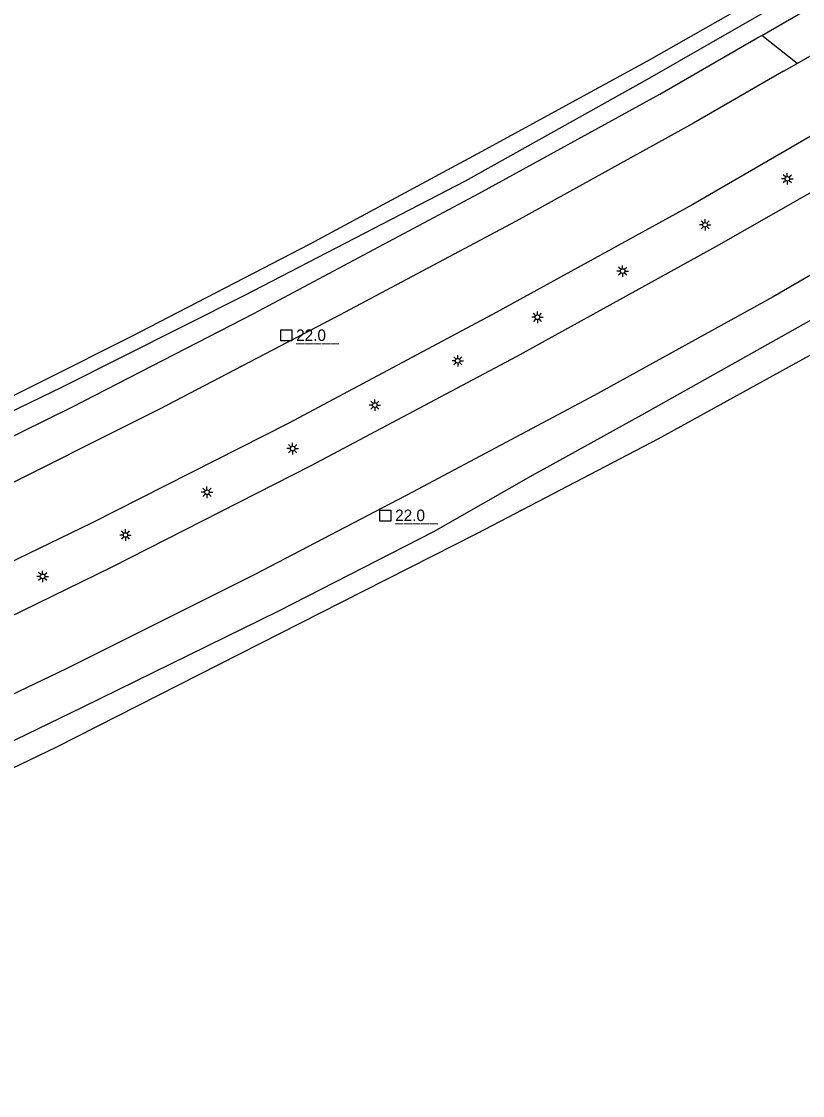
# Model space of a CAD drawing. Extents: x 124000 to 129000, y 395500 to 397503.
# Drawn here: x 125483 to 125568.1, y 397250 to 397367.1 of the extents above; entities that cross this region are included whole.
import ezdxf

# ---------------------------------------------------------------- set-up
doc = ezdxf.new("R2010")
doc.units = 0
for name, color, linetype in [('gg-knt-verharding', 7, 'Continuous'), ('gg-kntw-bovenkant insteek waterloop', 7, 'Continuous'), ('gt-anno-nummer hm paal', 7, 'Continuous'), ('gt-grn-groengrens', 7, 'Continuous'), ('gt-symb-hm paal', 7, 'Continuous'), ('gt-symb-lichtmast', 7, 'Continuous'), ('gx-grn-maaiveld', 7, 'Continuous')]:
    doc.layers.add(name, color=color, linetype=linetype)

# ---------------------------------------------------------------- blocks, each defined once
blk = doc.blocks.new('gt0-HMpaal')
at = {"layer": 'gt-symb-hm paal'}
blk.add_lwpolyline([(-0.6, 0.6), (0.6, 0.6), (0.6, -0.6), (-0.6, -0.6)], close=True, dxfattribs=at)
blk = doc.blocks.new('gt0-LMAST')
at = {"layer": 'gt-symb-lichtmast'}
for p, q in [((-0.18, 0.17), (-0.45, 0.44)), ((-0.01, 0.25), (-0.01, 0.62)), ((0.17, 0.17), (0.44, 0.44)), ((-0.26, 0), (-0.63, 0)), ((-0.18, -0.18), (-0.45, -0.45)), ((-0.01, -0.25), (-0.01, -0.63)), ((0.44, -0.45), (0.17, -0.18)), ((0.24, 0), (0.62, 0))]:
    blk.add_line(p, q, dxfattribs=at)
blk.add_circle((-0.01, 0), 0.25, dxfattribs=at)

msp = doc.modelspace()

# ---------------------------------------------------------------- linework, layer by layer
at = {"layer": 'gg-knt-verharding'}
msp.add_line((125566.04, 397361.66), (125567.52, 397362.52), dxfattribs=at)
for points in [[(125567.52, 397362.52), (125585.13, 397372.73), (125603.21, 397383.76), (125621.72, 397395.29), (125640.08, 397407.25), (125658.28, 397419.4), (125675.77, 397431.43), (125694.33, 397444.57), (125712.08, 397457.47), (125728.99, 397470.42), (125745.9, 397483.45), (125762.67, 397496.87), (125766.45, 397500)], [(125566.04, 397361.66), (125556.2, 397356.01), (125536.88, 397345.32), (125517.66, 397335.09), (125498.04, 397324.83), (125478.42, 397315.04), (125473.92, 397312.87)], [(125573.94, 397357.46), (125556.13, 397347.16), (125534.72, 397335.38), (125512.12, 397323.32), (125490.61, 397312.41), (125467.71, 397301.33), (125445.04, 397290.75), (125422.65, 397280.78), (125402.74, 397272.26), (125381.07, 397263.36), (125360.35, 397255.08), (125343.85, 397248.87), (125325.72, 397242.33), (125304.81, 397235.06), (125281.95, 397227.25), (125261.44, 397219.96), (125217.98, 397203.36), (125198.47, 397195.39)], [(125420.35, 397273.93), (125425.18, 397275.99), (125447.4, 397285.97), (125470.02, 397296.51), (125492.88, 397307.68), (125514.57, 397318.71), (125536.92, 397330.6), (125558.73, 397342.59), (125578.47, 397353.88)], [(125584.98, 397348.73), (125564.89, 397337.09), (125545.39, 397326.35), (125525.61, 397315.8), (125508.51, 397306.86), (125487.88, 397296.53), (125467.04, 397286.59), (125445.4, 397276.62), (125423.85, 397267.02)]]:
    msp.add_lwpolyline(points, dxfattribs=at)
at = {"layer": 'gg-kntw-bovenkant insteek waterloop'}
msp.add_line((125563.23, 397365.34), (125563.65, 397365.58), dxfattribs=at)
for points in [[(125563.65, 397365.58), (125573.92, 397371.52), (125596.7, 397385.02), (125618.83, 397398.69), (125639.49, 397412.34), (125659.03, 397425.34), (125680.13, 397440.12), (125700.39, 397454.72), (125720.23, 397469.47), (125739.7, 397484.43), (125758.84, 397499.72), (125759.17, 397500)], [(125564.86, 397368.6), (125551.16, 397360.77), (125531.35, 397349.7), (125507.23, 397337.21), (125487.34, 397327.22), (125467.81, 397317.76), (125448.4, 397308.53)], [(125449.32, 397306.34), (125469.1, 397315.52), (125488.57, 397325.1), (125508.32, 397335.28), (125532.83, 397348.35), (125552.54, 397359.17), (125563.23, 397365.34)], [(125539.23, 397317.94), (125550.6, 397324.21), (125570.6, 397335.46), (125588.54, 397345.93)], [(125590.79, 397343.67), (125572.37, 397332.61), (125552.33, 397321.59), (125532.64, 397311.29), (125517.82, 397303.76), (125486.83, 397288.02), (125473.03, 397281.39), (125454.9, 397272.8), (125445.58, 397268.58), (125421.67, 397258.05), (125405.46, 397251.51), (125400.1, 397249.35)], [(125539.23, 397317.94), (125527.89, 397311.48), (125511.01, 397302.84), (125489.62, 397292.32), (125469.13, 397282.43), (125447.03, 397272.28), (125424.39, 397262.32), (125401.77, 397252.72), (125381.29, 397244.39), (125360.75, 397236.55), (125340.81, 397229.01), (125320.17, 397221.71), (125298.76, 397214.49), (125285.55, 397209.76), (125273.27, 397205.54), (125262.61, 397201.4), (125240.33, 397192.92), (125217.68, 397183.58), (125207.14, 397179.11)]]:
    msp.add_lwpolyline(points, dxfattribs=at)
at = {"layer": 'gt-grn-groengrens'}
msp.add_line((125567.52, 397362.52), (125563.65, 397365.58), dxfattribs=at)
at = {"layer": 'gx-grn-maaiveld'}
msp.add_lwpolyline([(125562.79, 397369.41), (125560.46, 397368.04), (125551.4, 397362.86), (125533.14, 397352.93), (125514.42, 397342.84), (125494.92, 397332.71), (125476, 397323.23), (125451.7, 397311.59), (125432.13, 397302.47), (125410.97, 397293.11), (125390.71, 397284.58), (125368.71, 397275.64), (125350.23, 397268.51), (125344.47, 397266.41)], dxfattribs=at)

# ---------------------------------------------------------------- block references
at = {"layer": 'gt-symb-hm paal'}
for p in [(125511.84, 397332.88), (125522.63, 397313.25)]:
    msp.add_blockref('gt0-HMpaal', p, dxfattribs=at)
at = {"layer": 'gt-symb-lichtmast'}
for p in [(125566.45, 397349.94), (125557.49, 397344.93), (125548.51, 397339.89), (125539.22, 397334.86), (125530.54, 397330.12), (125521.51, 397325.29), (125512.55, 397320.55), (125503.22, 397315.79), (125494.34, 397311.13), (125485.31, 397306.62)]:
    msp.add_blockref('gt0-LMAST', p, dxfattribs=at)

# ---------------------------------------------------------------- texts
at = {"layer": 'gt-anno-nummer hm paal'}
for p in [(125512.92, 397332.28), (125523.71, 397312.65)]:
    msp.add_text('22.0', height=1.25, dxfattribs=at).set_placement(p)
at = {"layer": 'gt-symb-hm paal'}
for p in [(125512.92, 397332.28), (125523.71, 397312.65)]:
    msp.add_text('_____', height=1.25, dxfattribs=at).set_placement(p)

doc.saveas('drawing.dxf')
